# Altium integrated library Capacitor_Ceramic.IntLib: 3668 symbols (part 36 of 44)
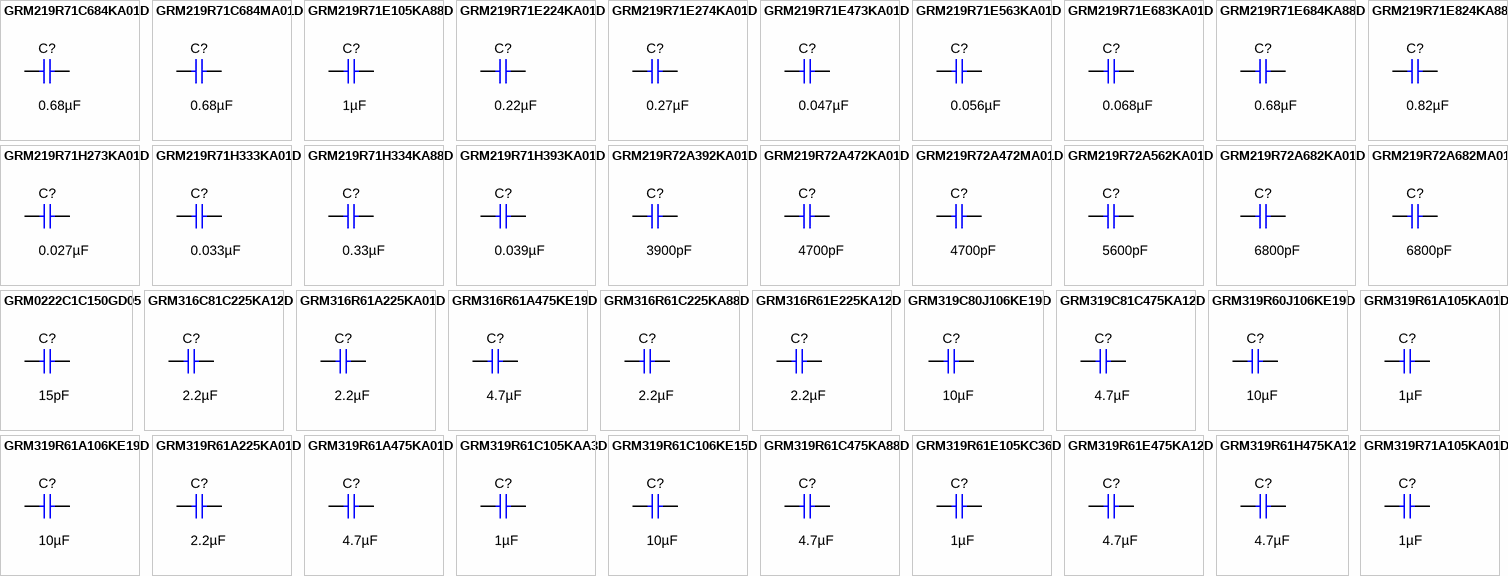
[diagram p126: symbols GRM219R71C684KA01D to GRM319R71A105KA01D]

## GRM219R71H334KA88D
designator C?  ValueDisplayed: 0.33µF  (hidden comment: GRM219R71H334KA88D)
CAP, CERM, 0.33 µF, 50 V,+/- 10%, X7R, 0805; Manufacturer: MuRata; Polarized: N; CompType: Capacitor; Value: 0.33uF; U/M: EA; Cap_F: 0.00000033; Tolerance_%: 10; VDC_V: 50; Value2: 50V; TaMin_C: -55; TaMax_C: 125; Cap_Case: 0805; SizeArea_mm2: 2.5; SizeAreaWB_mm2: 6.75; SizeX_mm: 2; SizeY_mm: 1.25; SizeZ_mm: 1.45; AEC Category: Q200; Green_Lifecycle: Active; Green_REACh: Passed
signal-integrity model Cap
simulation model Cap
footprint 0805_HV
footprint 0805_HV1
footprint 0805
footprint 0805M
footprint 0805L
pins: 1, 2

## GRM219R71H393KA01D
designator C?  ValueDisplayed: 0.039µF  (hidden comment: GRM219R71H393KA01D)
CAP, CERM, 0.039 µF, 50 V,+/- 10%, X7R, 0805; Manufacturer: MuRata; Polarized: N; CompType: Capacitor; Value: 0.039uF; U/M: EA; Cap_F: 0.000000039; Tolerance_%: 10; VDC_V: 50; Value2: 50V; TaMin_C: -55; TaMax_C: 125; Cap_Case: 0805; SizeArea_mm2: 2.5; SizeAreaWB_mm2: 6.75; SizeX_mm: 2; SizeY_mm: 1.25; SizeZ_mm: 1.45; AEC Category: Q200
signal-integrity model Cap
simulation model Cap
footprint 0805_HV
footprint 0805_HV1
footprint 0805
footprint 0805M
footprint 0805L
pins: 1, 2

## GRM219R72A392KA01D
designator C?  ValueDisplayed: 3900pF  (hidden comment: GRM219R72A392KA01D)
CAP, CERM, 3900 pF, 100 V,+/- 10%, X7R, 0805; Manufacturer: MuRata; Polarized: N; CompType: Capacitor; Value: 3900pF; U/M: EA; Cap_F: 0.0000000039; Tolerance_%: 10; VDC_V: 100; Value2: 100V; TaMin_C: -55; TaMax_C: 125; Cap_Case: 0805; SizeArea_mm2: 2.5; SizeAreaWB_mm2: 6.75; SizeX_mm: 2; SizeY_mm: 1.25; SizeZ_mm: 1.45; AEC Category: Q200
signal-integrity model Cap
simulation model Cap
footprint 0805_HV
footprint 0805_HV1
footprint 0805
footprint 0805M
footprint 0805L
pins: 1, 2

## GRM219R72A472KA01D
designator C?  ValueDisplayed: 4700pF  (hidden comment: GRM219R72A472KA01D)
CAP, CERM, 4700 pF, 100 V,+/- 10%, X7R, 0805; Manufacturer: MuRata; Polarized: N; CompType: Capacitor; Value: 4700pF; U/M: EA; Cap_F: 0.0000000047; Tolerance_%: 10; VDC_V: 100; Value2: 100V; TaMin_C: -55; TaMax_C: 125; Cap_Case: 0805; SizeArea_mm2: 2.5; SizeAreaWB_mm2: 6.75; SizeX_mm: 2; SizeY_mm: 1.25; SizeZ_mm: 1.45; AEC Category: Q200
signal-integrity model Cap
simulation model Cap
footprint 0805_HV
footprint 0805_HV1
footprint 0805
footprint 0805M
footprint 0805L
pins: 1, 2

## GRM219R72A472MA01D
designator C?  ValueDisplayed: 4700pF  (hidden comment: GRM219R72A472MA01D)
CAP, CERM, 4700 pF, 100 V,+/- 20%, X7R, 0805; Manufacturer: MuRata; Polarized: N; CompType: Capacitor; Value: 4700pF; U/M: EA; Cap_F: 0.0000000047; Tolerance_%: 20; VDC_V: 100; Value2: 100V; TaMin_C: -55; TaMax_C: 125; Cap_Case: 0805; SizeArea_mm2: 2.5; SizeAreaWB_mm2: 6.75; SizeX_mm: 2; SizeY_mm: 1.25; SizeZ_mm: 1.45; AEC Category: Q200
signal-integrity model Cap
simulation model Cap
footprint 0805_HV
footprint 0805_HV1
footprint 0805
footprint 0805M
footprint 0805L
pins: 1, 2

## GRM219R72A562KA01D
designator C?  ValueDisplayed: 5600pF  (hidden comment: GRM219R72A562KA01D)
CAP, CERM, 5600 pF, 100 V,+/- 10%, X7R, 0805; Manufacturer: MuRata; Polarized: N; CompType: Capacitor; Value: 5600pF; U/M: EA; Cap_F: 0.0000000056; Tolerance_%: 10; VDC_V: 100; Value2: 100V; TaMin_C: -55; TaMax_C: 125; Cap_Case: 0805; SizeArea_mm2: 2.5; SizeAreaWB_mm2: 6.75; SizeX_mm: 2; SizeY_mm: 1.25; SizeZ_mm: 1.45; AEC Category: Q200
signal-integrity model Cap
simulation model Cap
footprint 0805_HV
footprint 0805_HV1
footprint 0805
footprint 0805M
footprint 0805L
pins: 1, 2

## GRM219R72A682KA01D
designator C?  ValueDisplayed: 6800pF  (hidden comment: GRM219R72A682KA01D)
CAP, CERM, 6800 pF, 100 V,+/- 10%, X7R, 0805; Manufacturer: MuRata; Polarized: N; CompType: Capacitor; Value: 6800pF; U/M: EA; Cap_F: 0.0000000068; Tolerance_%: 10; VDC_V: 100; Value2: 100V; TaMin_C: -55; TaMax_C: 125; Cap_Case: 0805; SizeArea_mm2: 2.5; SizeAreaWB_mm2: 6.75; SizeX_mm: 2; SizeY_mm: 1.25; SizeZ_mm: 1.45; AEC Category: Q200
signal-integrity model Cap
simulation model Cap
footprint 0805_HV
footprint 0805_HV1
footprint 0805
footprint 0805M
footprint 0805L
pins: 1, 2

## GRM219R72A682MA01D
designator C?  ValueDisplayed: 6800pF  (hidden comment: GRM219R72A682MA01D)
CAP, CERM, 6800 pF, 100 V,+/- 20%, X7R, 0805; Manufacturer: MuRata; Polarized: N; CompType: Capacitor; Value: 6800pF; U/M: EA; Cap_F: 0.0000000068; Tolerance_%: 20; VDC_V: 100; Value2: 100V; TaMin_C: -55; TaMax_C: 125; Cap_Case: 0805; SizeArea_mm2: 2.5; SizeAreaWB_mm2: 6.75; SizeX_mm: 2; SizeY_mm: 1.25; SizeZ_mm: 1.45; AEC Category: Q200
signal-integrity model Cap
simulation model Cap
footprint 0805_HV
footprint 0805_HV1
footprint 0805
footprint 0805M
footprint 0805L
pins: 1, 2

## GRM0222C1C150GD05
designator C?  ValueDisplayed: 15pF  (hidden comment: GRM0222C1C150GD05)
CAP, CERM, 15 pF, 16 V,+/- 2%, C0G/NP0, 01005; Manufacturer: MuRata; Polarized: N; CompType: Capacitor; Value: 15pF; U/M: EA; Cap_F: 0.000000000015; Tolerance_%: 2; VDC_V: 16; Value2: 16V; TaMin_C: -55; TaMax_C: 125; Cap_Case: 01005; SizeArea_mm2: 0.08; SizeAreaWB_mm2: 1.68; SizeX_mm: 0.4; SizeY_mm: 0.2; AEC Category: Q200; Green_Lifecycle: Not Set; Green_REACh: Incomplete
signal-integrity model Cap
simulation model Cap
footprint 01005
pins: 1, 2

## GRM316C81C225KA12D
designator C?  ValueDisplayed: 2.2µF  (hidden comment: GRM316C81C225KA12D)
CAP, CERM, 2.2 µF, 16 V,+/- 10%, X6S, 1206; Manufacturer: MuRata; Polarized: N; CompType: Capacitor; Value: 2.2uF; U/M: EA; Cap_F: 0.0000022; Tolerance_%: 10; VDC_V: 16; Value2: 16V; TaMin_C: -55; TaMax_C: 105; Cap_Case: 1206; SizeArea_mm2: 5.12; SizeAreaWB_mm2: 10.92; SizeX_mm: 3.2; SizeY_mm: 1.6; SizeZ_mm: 1.35; AEC Category: Q200
signal-integrity model Cap
simulation model Cap
footprint 1206
footprint 1206M
footprint 1206L
pins: 1, 2

## GRM316R61A225KA01D
designator C?  ValueDisplayed: 2.2µF  (hidden comment: GRM316R61A225KA01D)
CAP, CERM, 2.2 µF, 10 V,+/- 10%, X5R, 1206; Manufacturer: MuRata; Polarized: N; CompType: Capacitor; Value: 2.2uF; U/M: EA; Cap_F: 0.0000022; Tolerance_%: 10; Value2: 10V; TaMin_C: -55; TaMax_C: 85; Cap_Case: 1206; SizeArea_mm2: 5.12; SizeAreaWB_mm2: 10.92; SizeX_mm: 3.2; SizeY_mm: 1.6; SizeZ_mm: 1.35; AEC Category: Q200
signal-integrity model Cap
simulation model Cap
footprint 1206
footprint 1206M
footprint 1206L
pins: 1, 2

## GRM316R61A475KE19D
designator C?  ValueDisplayed: 4.7µF  (hidden comment: GRM316R61A475KE19D)
CAP, CERM, 4.7 µF, 10 V,+/- 10%, X5R, 1206; Manufacturer: MuRata; Polarized: N; CompType: Capacitor; Value: 4.7uF; U/M: EA; Cap_F: 0.0000047; Tolerance_%: 10; ESR_ohm: 0.007; Value1: 0.007 ohm; Value2: 10V; TaMin_C: -55; TaMax_C: 85; Cap_Case: 1206; SizeArea_mm2: 5.12; SizeAreaWB_mm2: 10.92; SizeX_mm: 3.2; SizeY_mm: 1.6; SizeZ_mm: 1.35; AEC Category: Q200
signal-integrity model Cap
simulation model Cap
footprint 1206
footprint 1206M
footprint 1206L
pins: 1, 2

## GRM316R61C225KA88D
designator C?  ValueDisplayed: 2.2µF  (hidden comment: GRM316R61C225KA88D)
CAP, CERM, 2.2 µF, 16 V,+/- 10%, X5R, 1206; Manufacturer: MuRata; Polarized: N; CompType: Capacitor; Value: 2.2uF; U/M: EA; Cap_F: 0.0000022; Tolerance_%: 10; VDC_V: 16; Value2: 16V; TaMin_C: -55; TaMax_C: 85; Cap_Case: 1206; SizeArea_mm2: 5.12; SizeAreaWB_mm2: 10.92; SizeX_mm: 3.2; SizeY_mm: 1.6; SizeZ_mm: 1.35; AEC Category: Q200
signal-integrity model Cap
simulation model Cap
footprint 1206
footprint 1206M
footprint 1206L
pins: 1, 2

## GRM316R61E225KA12D
designator C?  ValueDisplayed: 2.2µF  (hidden comment: GRM316R61E225KA12D)
CAP, CERM, 2.2 µF, 25 V,+/- 10%, X5R, 1206; Manufacturer: MuRata; Polarized: N; CompType: Capacitor; Value: 2.2uF; U/M: EA; Cap_F: 0.0000022; Tolerance_%: 10; ESR_ohm: 0.006; Value1: 0.006 ohm; VDC_V: 25; Value2: 25V; TaMin_C: -55; TaMax_C: 85; Cap_Case: 1206; SizeArea_mm2: 5.12; SizeAreaWB_mm2: 10.92; SizeX_mm: 3.2; SizeY_mm: 1.6; SizeZ_mm: 1.35; AEC Category: Q200; Green_Lifecycle: Active; Green_REACh: Passed
signal-integrity model Cap
simulation model Cap
footprint 1206
footprint 1206M
footprint 1206L
pins: 1, 2

## GRM319C80J106KE19D
designator C?  ValueDisplayed: 10µF  (hidden comment: GRM319C80J106KE19D)
CAP, CERM, 10 µF, 6.3 V,+/- 10%, X6S, 1206; Manufacturer: MuRata; Polarized: N; CompType: Capacitor; Value: 10uF; U/M: EA; Cap_F: 0.00001; Tolerance_%: 10; VDC_V: 6.3; Value2: 6.3V; TaMin_C: -55; TaMax_C: 105; Cap_Case: 1206; SizeArea_mm2: 5.12; SizeAreaWB_mm2: 10.92; SizeX_mm: 3.2; SizeY_mm: 1.6; SizeZ_mm: 1.35; AEC Category: Q200
signal-integrity model Cap
simulation model Cap
footprint 1206
footprint 1206M
footprint 1206L
pins: 1, 2

## GRM319C81C475KA12D
designator C?  ValueDisplayed: 4.7µF  (hidden comment: GRM319C81C475KA12D)
CAP, CERM, 4.7 µF, 16 V,+/- 10%, X6S, 1206; Manufacturer: MuRata; Polarized: N; CompType: Capacitor; Value: 4.7uF; U/M: EA; Cap_F: 0.0000047; Tolerance_%: 10; VDC_V: 16; Value2: 16V; TaMin_C: -55; TaMax_C: 105; Cap_Case: 1206; SizeArea_mm2: 5.12; SizeAreaWB_mm2: 10.92; SizeX_mm: 3.2; SizeY_mm: 1.6; SizeZ_mm: 1.35; AEC Category: Q200
signal-integrity model Cap
simulation model Cap
footprint 1206
footprint 1206M
footprint 1206L
pins: 1, 2

## GRM319R60J106KE19D
designator C?  ValueDisplayed: 10µF  (hidden comment: GRM319R60J106KE19D)
CAP, CERM, 10 µF, 6.3 V,+/- 10%, X5R, 1206; Manufacturer: MuRata; Polarized: N; CompType: Capacitor; Value: 10uF; U/M: EA; Cap_F: 0.00001; Tolerance_%: 10; VDC_V: 6.3; Value2: 6.3V; TaMin_C: -55; TaMax_C: 85; Cap_Case: 1206; SizeArea_mm2: 5.12; SizeAreaWB_mm2: 10.92; SizeX_mm: 3.2; SizeY_mm: 1.6; SizeZ_mm: 1.35; AEC Category: Q200
signal-integrity model Cap
simulation model Cap
footprint 1206
footprint 1206M
footprint 1206L
pins: 1, 2

## GRM319R61A105KA01D
designator C?  ValueDisplayed: 1µF  (hidden comment: GRM319R61A105KA01D)
CAP, CERM, 1 µF, 10 V,+/- 10%, X5R, 1206; Manufacturer: MuRata; Polarized: N; CompType: Capacitor; Value: 1uF; U/M: EA; Cap_F: 0.000001; Tolerance_%: 10; Value2: 10V; TaMin_C: -55; TaMax_C: 85; Cap_Case: 1206; SizeArea_mm2: 5.12; SizeAreaWB_mm2: 10.92; SizeX_mm: 3.2; SizeY_mm: 1.6; SizeZ_mm: 1.35; AEC Category: Q200
signal-integrity model Cap
simulation model Cap
footprint 1206
footprint 1206M
footprint 1206L
pins: 1, 2

## GRM319R61A106KE19D
designator C?  ValueDisplayed: 10µF  (hidden comment: GRM319R61A106KE19D)
CAP, CERM, 10 µF, 10 V,+/- 10%, X5R, 1206; Manufacturer: MuRata; Polarized: N; CompType: Capacitor; Value: 10uF; U/M: EA; Cap_F: 0.00001; Tolerance_%: 10; ESR_ohm: 0.004; Value1: 0.004 ohm; Value2: 10V; TaMin_C: -55; TaMax_C: 85; Cap_Case: 1206; SizeArea_mm2: 5.12; SizeAreaWB_mm2: 10.92; SizeX_mm: 3.2; SizeY_mm: 1.6; SizeZ_mm: 1.35; AEC Category: Q200
signal-integrity model Cap
simulation model Cap
footprint 1206
footprint 1206M
footprint 1206L
pins: 1, 2

## GRM319R61A225KA01D
designator C?  ValueDisplayed: 2.2µF  (hidden comment: GRM319R61A225KA01D)
CAP, CERM, 2.2 µF, 10 V,+/- 10%, X5R, 1206; Manufacturer: MuRata; Polarized: N; CompType: Capacitor; Value: 2.2uF; U/M: EA; Cap_F: 0.0000022; Tolerance_%: 10; ESR_ohm: 0.009; Value1: 0.009 ohm; Value2: 10V; TaMin_C: -55; TaMax_C: 85; Cap_Case: 1206; SizeArea_mm2: 5.12; SizeAreaWB_mm2: 10.92; SizeX_mm: 3.2; SizeY_mm: 1.6; SizeZ_mm: 1.35; AEC Category: Q200
signal-integrity model Cap
simulation model Cap
footprint 1206
footprint 1206M
footprint 1206L
pins: 1, 2

## GRM319R61A475KA01D
designator C?  ValueDisplayed: 4.7µF  (hidden comment: GRM319R61A475KA01D)
CAP, CERM, 4.7 µF, 10 V,+/- 10%, X5R, 1206; Manufacturer: MuRata; Polarized: N; CompType: Capacitor; Value: 4.7uF; U/M: EA; Cap_F: 0.0000047; Tolerance_%: 10; Value2: 10V; TaMin_C: -55; TaMax_C: 85; Cap_Case: 1206; SizeArea_mm2: 5.12; SizeAreaWB_mm2: 10.92; SizeX_mm: 3.2; SizeY_mm: 1.6; SizeZ_mm: 1.35; AEC Category: Q200
signal-integrity model Cap
simulation model Cap
footprint 1206
footprint 1206M
footprint 1206L
pins: 1, 2

## GRM319R61C105KAA3D
designator C?  ValueDisplayed: 1µF  (hidden comment: GRM319R61C105KAA3D)
CAP, CERM, 1 µF, 16 V,+/- 10%, X5R, 1206; Manufacturer: MuRata; Polarized: N; CompType: Capacitor; Value: 1uF; U/M: EA; Cap_F: 0.000001; Tolerance_%: 10; VDC_V: 16; Value2: 16V; TaMin_C: -55; TaMax_C: 85; Cap_Case: 1206; SizeArea_mm2: 5.12; SizeAreaWB_mm2: 10.92; SizeX_mm: 3.2; SizeY_mm: 1.6; SizeZ_mm: 1.35; AEC Category: Q200
signal-integrity model Cap
simulation model Cap
footprint 1206
footprint 1206M
footprint 1206L
pins: 1, 2

## GRM319R61C106KE15D
designator C?  ValueDisplayed: 10µF  (hidden comment: GRM319R61C106KE15D)
CAP, CERM, 10 µF, 16 V,+/- 10%, X5R, 1206; Manufacturer: MuRata; Polarized: N; CompType: Capacitor; Value: 10uF; U/M: EA; Cap_F: 0.00001; Tolerance_%: 10; VDC_V: 16; Value2: 16V; TaMin_C: -55; TaMax_C: 85; Cap_Case: 1206; SizeArea_mm2: 5.12; SizeAreaWB_mm2: 10.92; SizeX_mm: 3.2; SizeY_mm: 1.6; SizeZ_mm: 1.35; AEC Category: Q200
signal-integrity model Cap
simulation model Cap
footprint 1206
footprint 1206M
footprint 1206L
pins: 1, 2

## GRM319R61C475KA88D
designator C?  ValueDisplayed: 4.7µF  (hidden comment: GRM319R61C475KA88D)
CAP, CERM, 4.7 µF, 16 V,+/- 10%, X5R, 1206; Manufacturer: MuRata; Polarized: N; CompType: Capacitor; Value: 4.7uF; U/M: EA; Cap_F: 0.0000047; Tolerance_%: 10; VDC_V: 16; Value2: 16V; TaMin_C: -55; TaMax_C: 85; Cap_Case: 1206; SizeArea_mm2: 5.12; SizeAreaWB_mm2: 10.92; SizeX_mm: 3.2; SizeY_mm: 1.6; SizeZ_mm: 1.35; AEC Category: Q200
signal-integrity model Cap
simulation model Cap
footprint 1206
footprint 1206M
footprint 1206L
pins: 1, 2

## GRM319R61E105KC36D
designator C?  ValueDisplayed: 1µF  (hidden comment: GRM319R61E105KC36D)
CAP, CERM, 1 µF, 25 V,+/- 10%, X5R, 1206; Manufacturer: MuRata; Polarized: N; CompType: Capacitor; Value: 1uF; U/M: EA; Cap_F: 0.000001; Tolerance_%: 10; ESR_ohm: 0.01; Value1: 0.01 ohm; VDC_V: 25; Value2: 25V; TaMin_C: -55; TaMax_C: 85; Cap_Case: 1206; SizeArea_mm2: 5.12; SizeAreaWB_mm2: 10.92; SizeX_mm: 3.2; SizeY_mm: 1.6; SizeZ_mm: 1.35; AEC Category: Q200
signal-integrity model Cap
simulation model Cap
footprint 1206
footprint 1206M
footprint 1206L
pins: 1, 2

## GRM319R61E475KA12D
designator C?  ValueDisplayed: 4.7µF  (hidden comment: GRM319R61E475KA12D)
CAP, CERM, 4.7 µF, 25 V,+/- 10%, X5R, 1206; Manufacturer: MuRata; Polarized: N; CompType: Capacitor; Value: 4.7uF; U/M: EA; Cap_F: 0.0000047; Tolerance_%: 10; ESR_ohm: 0.006; Value1: 0.006 ohm; VDC_V: 25; Value2: 25V; TaMin_C: -55; TaMax_C: 85; Cap_Case: 1206; SizeArea_mm2: 5.12; SizeAreaWB_mm2: 10.92; SizeX_mm: 3.2; SizeY_mm: 1.6; SizeZ_mm: 1.35; AEC Category: Q200
signal-integrity model Cap
simulation model Cap
footprint 1206
footprint 1206M
footprint 1206L
pins: 1, 2

## GRM319R61H475KA12
designator C?  ValueDisplayed: 4.7µF  (hidden comment: GRM319R61H475KA12)
CAP, CERM, 4.7 µF, 50 V,+/- 10%, X5R, 1206; Manufacturer: MuRata; Polarized: N; CompType: Capacitor; Value: 4.7uF; U/M: EA; Cap_F: 0.0000047; Tolerance_%: 10; VDC_V: 50; Value2: 50V; TaMin_C: -55; TaMax_C: 85; Cap_Case: 1206; SizeArea_mm2: 5.12; SizeAreaWB_mm2: 10.92; SizeX_mm: 3.2; SizeY_mm: 1.6; SizeZ_mm: 1.35; AEC Category: Q200; Green_Lifecycle: Active; Green_REACh: Passed
signal-integrity model Cap
simulation model Cap
footprint 1206
footprint 1206M
footprint 1206L
pins: 1, 2

## GRM319R71A105KA01D
designator C?  ValueDisplayed: 1µF  (hidden comment: GRM319R71A105KA01D)
CAP, CERM, 1 µF, 10 V,+/- 10%, X7R, 1206; Manufacturer: MuRata; Polarized: N; CompType: Capacitor; Value: 1uF; U/M: EA; Cap_F: 0.000001; Tolerance_%: 10; Value2: 10V; TaMin_C: -55; TaMax_C: 125; Cap_Case: 1206; SizeArea_mm2: 5.12; SizeAreaWB_mm2: 10.92; SizeX_mm: 3.2; SizeY_mm: 1.6; SizeZ_mm: 1.35; AEC Category: Q200
signal-integrity model Cap
simulation model Cap
footprint 1206
footprint 1206M
footprint 1206L
pins: 1, 2

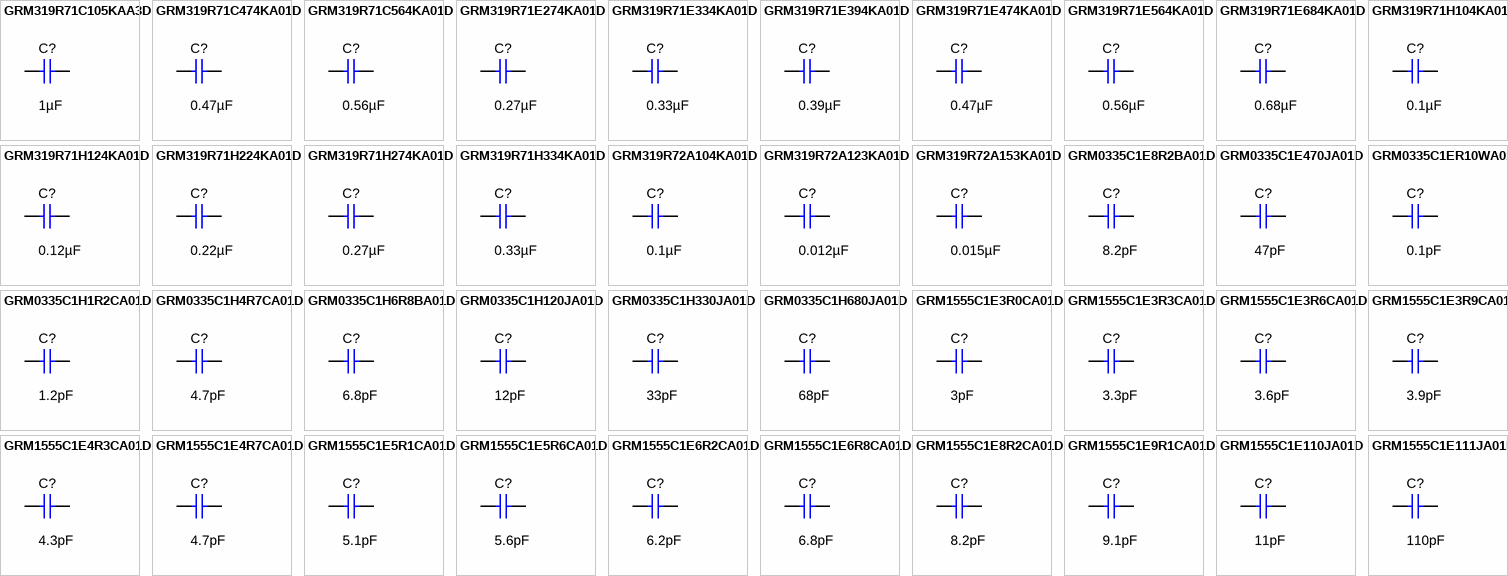
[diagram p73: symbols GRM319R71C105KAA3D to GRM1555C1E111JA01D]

## GRM319R71C105KAA3D
designator C?  ValueDisplayed: 1µF  (hidden comment: GRM319R71C105KAA3D)
CAP, CERM, 1 µF, 16 V,+/- 10%, X7R, 1206; Manufacturer: MuRata; Polarized: N; CompType: Capacitor; Value: 1uF; U/M: EA; Cap_F: 0.000001; Tolerance_%: 10; VDC_V: 16; Value2: 16V; TaMin_C: -55; TaMax_C: 125; Cap_Case: 1206; SizeArea_mm2: 5.12; SizeAreaWB_mm2: 10.92; SizeX_mm: 3.2; SizeY_mm: 1.6; SizeZ_mm: 1.35; AEC Category: Q200
signal-integrity model Cap
simulation model Cap
footprint 1206
footprint 1206M
footprint 1206L
pins: 1, 2

## GRM319R71C474KA01D
designator C?  ValueDisplayed: 0.47µF  (hidden comment: GRM319R71C474KA01D)
CAP, CERM, 0.47 µF, 16 V,+/- 10%, X7R, 1206; Manufacturer: MuRata; Polarized: N; CompType: Capacitor; Value: 0.47uF; U/M: EA; Cap_F: 0.00000047; Tolerance_%: 10; VDC_V: 16; Value2: 16V; TaMin_C: -55; TaMax_C: 125; Cap_Case: 1206; SizeArea_mm2: 5.12; SizeAreaWB_mm2: 10.92; SizeX_mm: 3.2; SizeY_mm: 1.6; SizeZ_mm: 1.35; AEC Category: Q200
signal-integrity model Cap
simulation model Cap
footprint 1206
footprint 1206M
footprint 1206L
pins: 1, 2

## GRM319R71C564KA01D
designator C?  ValueDisplayed: 0.56µF  (hidden comment: GRM319R71C564KA01D)
CAP, CERM, 0.56 µF, 16 V,+/- 10%, X7R, 1206; Manufacturer: MuRata; Polarized: N; CompType: Capacitor; Value: 0.56uF; U/M: EA; Cap_F: 0.00000056; Tolerance_%: 10; VDC_V: 16; Value2: 16V; TaMin_C: -55; TaMax_C: 125; Cap_Case: 1206; SizeArea_mm2: 5.12; SizeAreaWB_mm2: 10.92; SizeX_mm: 3.2; SizeY_mm: 1.6; SizeZ_mm: 1.35; AEC Category: Q200
signal-integrity model Cap
simulation model Cap
footprint 1206
footprint 1206M
footprint 1206L
pins: 1, 2

## GRM319R71E274KA01D
designator C?  ValueDisplayed: 0.27µF  (hidden comment: GRM319R71E274KA01D)
CAP, CERM, 0.27 µF, 25 V,+/- 10%, X7R, 1206; Manufacturer: MuRata; Polarized: N; CompType: Capacitor; Value: 0.27uF; U/M: EA; Cap_F: 0.00000027; Tolerance_%: 10; VDC_V: 25; Value2: 25V; TaMin_C: -55; TaMax_C: 125; Cap_Case: 1206; SizeArea_mm2: 5.12; SizeAreaWB_mm2: 10.92; SizeX_mm: 3.2; SizeY_mm: 1.6; SizeZ_mm: 1.35; AEC Category: Q200
signal-integrity model Cap
simulation model Cap
footprint 1206
footprint 1206M
footprint 1206L
pins: 1, 2

## GRM319R71E334KA01D
designator C?  ValueDisplayed: 0.33µF  (hidden comment: GRM319R71E334KA01D)
CAP, CERM, 0.33 µF, 25 V,+/- 10%, X7R, 1206; Manufacturer: MuRata; Polarized: N; CompType: Capacitor; Value: 0.33uF; U/M: EA; Cap_F: 0.00000033; Tolerance_%: 10; VDC_V: 25; Value2: 25V; TaMin_C: -55; TaMax_C: 125; Cap_Case: 1206; SizeArea_mm2: 5.12; SizeAreaWB_mm2: 10.92; SizeX_mm: 3.2; SizeY_mm: 1.6; SizeZ_mm: 1.35; AEC Category: Q200
signal-integrity model Cap
simulation model Cap
footprint 1206
footprint 1206M
footprint 1206L
pins: 1, 2

## GRM319R71E394KA01D
designator C?  ValueDisplayed: 0.39µF  (hidden comment: GRM319R71E394KA01D)
CAP, CERM, 0.39 µF, 25 V,+/- 10%, X7R, 1206; Manufacturer: MuRata; Polarized: N; CompType: Capacitor; Value: 0.39uF; U/M: EA; Cap_F: 0.00000039; Tolerance_%: 10; VDC_V: 25; Value2: 25V; TaMin_C: -55; TaMax_C: 125; Cap_Case: 1206; SizeArea_mm2: 5.12; SizeAreaWB_mm2: 10.92; SizeX_mm: 3.2; SizeY_mm: 1.6; SizeZ_mm: 1.35; AEC Category: Q200
signal-integrity model Cap
simulation model Cap
footprint 1206
footprint 1206M
footprint 1206L
pins: 1, 2

## GRM319R71E474KA01D
designator C?  ValueDisplayed: 0.47µF  (hidden comment: GRM319R71E474KA01D)
CAP, CERM, 0.47 µF, 25 V,+/- 10%, X7R, 1206; Manufacturer: MuRata; Polarized: N; CompType: Capacitor; Value: 0.47uF; U/M: EA; Cap_F: 0.00000047; Tolerance_%: 10; VDC_V: 25; Value2: 25V; TaMin_C: -55; TaMax_C: 125; Cap_Case: 1206; SizeArea_mm2: 5.12; SizeAreaWB_mm2: 10.92; SizeX_mm: 3.2; SizeY_mm: 1.6; SizeZ_mm: 1.35; AEC Category: Q200
signal-integrity model Cap
simulation model Cap
footprint 1206
footprint 1206M
footprint 1206L
pins: 1, 2

## GRM319R71E564KA01D
designator C?  ValueDisplayed: 0.56µF  (hidden comment: GRM319R71E564KA01D)
CAP, CERM, 0.56 µF, 25 V,+/- 10%, X7R, 1206; Manufacturer: MuRata; Polarized: N; CompType: Capacitor; Value: 0.56uF; U/M: EA; Cap_F: 0.00000056; Tolerance_%: 10; VDC_V: 25; Value2: 25V; TaMin_C: -55; TaMax_C: 125; Cap_Case: 1206; SizeArea_mm2: 5.12; SizeAreaWB_mm2: 10.92; SizeX_mm: 3.2; SizeY_mm: 1.6; SizeZ_mm: 1.35; AEC Category: Q200
signal-integrity model Cap
simulation model Cap
footprint 1206
footprint 1206M
footprint 1206L
pins: 1, 2

## GRM319R71E684KA01D
designator C?  ValueDisplayed: 0.68µF  (hidden comment: GRM319R71E684KA01D)
CAP, CERM, 0.68 µF, 25 V,+/- 10%, X7R, 1206; Manufacturer: MuRata; Polarized: N; CompType: Capacitor; Value: 0.68uF; U/M: EA; Cap_F: 0.00000068; Tolerance_%: 10; VDC_V: 25; Value2: 25V; TaMin_C: -55; TaMax_C: 125; Cap_Case: 1206; SizeArea_mm2: 5.12; SizeAreaWB_mm2: 10.92; SizeX_mm: 3.2; SizeY_mm: 1.6; SizeZ_mm: 1.35; AEC Category: Q200
signal-integrity model Cap
simulation model Cap
footprint 1206
footprint 1206M
footprint 1206L
pins: 1, 2

## GRM319R71H104KA01D
designator C?  ValueDisplayed: 0.1µF  (hidden comment: GRM319R71H104KA01D)
CAP, CERM, 0.1 µF, 50 V,+/- 10%, X7R, 1206; Manufacturer: MuRata; Polarized: N; CompType: Capacitor; Value: 0.1uF; U/M: EA; Cap_F: 0.0000001; Tolerance_%: 10; ESR_ohm: 0.01; Value1: 0.01 ohm; VDC_V: 50; Value2: 50V; IRMS_A: 0.9; TaMin_C: -55; TaMax_C: 125; Cap_Case: 1206; SizeArea_mm2: 5.12; SizeAreaWB_mm2: 10.92; SizeX_mm: 3.2; SizeY_mm: 1.6; SizeZ_mm: 1.35; AEC Category: Q200; Green_Lifecycle: Active; Green_REACh: Passed
signal-integrity model Cap
simulation model Cap
footprint 1206
footprint 1206M
footprint 1206L
pins: 1, 2

## GRM319R71H124KA01D
designator C?  ValueDisplayed: 0.12µF  (hidden comment: GRM319R71H124KA01D)
CAP, CERM, 0.12 µF, 50 V,+/- 10%, X7R, 1206; Manufacturer: MuRata; Polarized: N; CompType: Capacitor; Value: 0.12uF; U/M: EA; Cap_F: 0.00000012; Tolerance_%: 10; VDC_V: 50; Value2: 50V; TaMin_C: -55; TaMax_C: 125; Cap_Case: 1206; SizeArea_mm2: 5.12; SizeAreaWB_mm2: 10.92; SizeX_mm: 3.2; SizeY_mm: 1.6; SizeZ_mm: 1.35; AEC Category: Q200
signal-integrity model Cap
simulation model Cap
footprint 1206
footprint 1206M
footprint 1206L
pins: 1, 2

## GRM319R71H224KA01D
designator C?  ValueDisplayed: 0.22µF  (hidden comment: GRM319R71H224KA01D)
CAP, CERM, 0.22 µF, 50 V,+/- 10%, X7R, 1206; Manufacturer: MuRata; Polarized: N; CompType: Capacitor; Value: 0.22uF; U/M: EA; Cap_F: 0.00000022; Tolerance_%: 10; ESR_ohm: 0.01; Value1: 0.01 ohm; VDC_V: 50; Value2: 50V; IRMS_A: 0.9; TaMin_C: -55; TaMax_C: 125; Cap_Case: 1206; SizeArea_mm2: 5.12; SizeAreaWB_mm2: 10.92; SizeX_mm: 3.2; SizeY_mm: 1.6; SizeZ_mm: 1.35; AEC Category: Q200
signal-integrity model Cap
simulation model Cap
footprint 1206
footprint 1206M
footprint 1206L
pins: 1, 2

## GRM319R71H274KA01D
designator C?  ValueDisplayed: 0.27µF  (hidden comment: GRM319R71H274KA01D)
CAP, CERM, 0.27 µF, 50 V,+/- 10%, X7R, 1206; Manufacturer: MuRata; Polarized: N; CompType: Capacitor; Value: 0.27uF; U/M: EA; Cap_F: 0.00000027; Tolerance_%: 10; VDC_V: 50; Value2: 50V; TaMin_C: -55; TaMax_C: 125; Cap_Case: 1206; SizeArea_mm2: 5.12; SizeAreaWB_mm2: 10.92; SizeX_mm: 3.2; SizeY_mm: 1.6; SizeZ_mm: 1.35; AEC Category: Q200
signal-integrity model Cap
simulation model Cap
footprint 1206
footprint 1206M
footprint 1206L
pins: 1, 2

## GRM319R71H334KA01D
designator C?  ValueDisplayed: 0.33µF  (hidden comment: GRM319R71H334KA01D)
CAP, CERM, 0.33 µF, 50 V,+/- 10%, X7R, 1206; Manufacturer: MuRata; Polarized: N; CompType: Capacitor; Value: 0.33uF; U/M: EA; Cap_F: 0.00000033; Tolerance_%: 10; VDC_V: 50; Value2: 50V; TaMin_C: -55; TaMax_C: 125; Cap_Case: 1206; SizeArea_mm2: 5.12; SizeAreaWB_mm2: 10.92; SizeX_mm: 3.2; SizeY_mm: 1.6; SizeZ_mm: 1.35; AEC Category: Q200; Green_Lifecycle: Active; Green_REACh: Passed
signal-integrity model Cap
simulation model Cap
footprint 1206
footprint 1206M
footprint 1206L
pins: 1, 2

## GRM319R72A104KA01D
designator C?  ValueDisplayed: 0.1µF  (hidden comment: GRM319R72A104KA01D)
CAP, CERM, 0.1 µF, 100 V,+/- 10%, X7R, 1206; Manufacturer: MuRata; Polarized: N; CompType: Capacitor; Value: 0.1uF; U/M: EA; Cap_F: 0.0000001; Tolerance_%: 10; VDC_V: 100; Value2: 100V; TaMin_C: -55; TaMax_C: 125; Cap_Case: 1206; SizeArea_mm2: 5.12; SizeAreaWB_mm2: 10.92; SizeX_mm: 3.2; SizeY_mm: 1.6; SizeZ_mm: 1.35; AEC Category: Q200
signal-integrity model Cap
simulation model Cap
footprint 1206
footprint 1206M
footprint 1206L
pins: 1, 2

## GRM319R72A123KA01D
designator C?  ValueDisplayed: 0.012µF  (hidden comment: GRM319R72A123KA01D)
CAP, CERM, 0.012 µF, 100 V,+/- 10%, X7R, 1206; Manufacturer: MuRata; Polarized: N; CompType: Capacitor; Value: 0.012uF; U/M: EA; Cap_F: 0.000000012; Tolerance_%: 10; VDC_V: 100; Value2: 100V; TaMin_C: -55; TaMax_C: 125; Cap_Case: 1206; SizeArea_mm2: 5.12; SizeAreaWB_mm2: 10.92; SizeX_mm: 3.2; SizeY_mm: 1.6; SizeZ_mm: 1.35; AEC Category: Q200
signal-integrity model Cap
simulation model Cap
footprint 1206
footprint 1206M
footprint 1206L
pins: 1, 2

## GRM319R72A153KA01D
designator C?  ValueDisplayed: 0.015µF  (hidden comment: GRM319R72A153KA01D)
CAP, CERM, 0.015 µF, 100 V,+/- 10%, X7R, 1206; Manufacturer: MuRata; Polarized: N; CompType: Capacitor; Value: 0.015uF; U/M: EA; Cap_F: 0.000000015; Tolerance_%: 10; VDC_V: 100; Value2: 100V; TaMin_C: -55; TaMax_C: 125; Cap_Case: 1206; SizeArea_mm2: 5.12; SizeAreaWB_mm2: 10.92; SizeX_mm: 3.2; SizeY_mm: 1.6; SizeZ_mm: 1.35; AEC Category: Q200
signal-integrity model Cap
simulation model Cap
footprint 1206
footprint 1206M
footprint 1206L
pins: 1, 2

## GRM0335C1E8R2BA01D
designator C?  ValueDisplayed: 8.2pF  (hidden comment: GRM0335C1E8R2BA01D)
CAP, CERM, 8.2 pF, 25 V,+/- 1.2%, C0G/NP0, 0201; Manufacturer: MuRata; Polarized: N; CompType: Capacitor; Value: 8.2pF; U/M: EA; Cap_F: 0.0000000000082; Tolerance_%: 1.2; VDC_V: 25; Value2: 25V; TaMin_C: -55; TaMax_C: 125; Cap_Case: 0201; SizeArea_mm2: 0.18; SizeAreaWB_mm2: 2.08; SizeX_mm: 0.6; SizeY_mm: 0.3; SizeZ_mm: 0.26; AEC Category: Q200
signal-integrity model Cap
simulation model Cap
footprint 0201
footprint 0201M
footprint 0201L
footprint 0201_Silk
pins: 1, 2

## GRM0335C1E470JA01D
designator C?  ValueDisplayed: 47pF  (hidden comment: GRM0335C1E470JA01D)
CAP, CERM, 47 pF, 25 V,+/- 5%, C0G/NP0, 0201; Manufacturer: MuRata; Polarized: N; CompType: Capacitor; Value: 47pF; U/M: EA; Cap_F: 0.000000000047; Tolerance_%: 5; VDC_V: 25; Value2: 25V; TaMin_C: -55; TaMax_C: 125; Cap_Case: 0201; SizeArea_mm2: 0.18; SizeAreaWB_mm2: 2.08; SizeX_mm: 0.6; SizeY_mm: 0.3; SizeZ_mm: 0.33; AEC Category: Q200; Green_Lifecycle: Active; Green_REACh: Passed
signal-integrity model Cap
simulation model Cap
footprint 0201_033
footprint 0201_033M
footprint 0201_033L
pins: 1, 2

## GRM0335C1ER10WA01D
designator C?  ValueDisplayed: 0.1pF  (hidden comment: GRM0335C1ER10WA01D)
CAP, CERM, 0.1pF, 25 V,+/- 50%, C0G/NP0, 0201; Manufacturer: MuRata; Polarized: N; CompType: Capacitor; U/M: EA; Cap_F: 0.0000000000001; Tolerance_%: 50; VDC_V: 25; Value2: 25V; TaMin_C: -55; TaMax_C: 125; Cap_Case: 0201; SizeArea_mm2: 0.18; SizeAreaWB_mm2: 2.08; SizeX_mm: 0.6; SizeY_mm: 0.3; SizeZ_mm: 0.33; AEC Category: Q200; Green_Lifecycle: Active; Green_REACh: Passed
signal-integrity model Cap
simulation model Cap
footprint 0201_033
footprint 0201_033M
footprint 0201_033L
pins: 1, 2

## GRM0335C1H1R2CA01D
designator C?  ValueDisplayed: 1.2pF  (hidden comment: GRM0335C1H1R2CA01D)
CAP, CERM, 1.2 pF, 50 V,+/- 20%, C0G/NP0, 0201; Manufacturer: MuRata; Polarized: N; CompType: Capacitor; Value: 1.2pF; U/M: EA; Cap_F: 0.0000000000012; Tolerance_%: 20; VDC_V: 50; Value2: 50V; TaMin_C: -55; TaMax_C: 125; Cap_Case: 0201; SizeArea_mm2: 0.18; SizeAreaWB_mm2: 2.08; SizeX_mm: 0.6; SizeY_mm: 0.3; SizeZ_mm: 0.26; AEC Category: Q200
signal-integrity model Cap
simulation model Cap
footprint 0201
footprint 0201M
footprint 0201L
footprint 0201_Silk
pins: 1, 2

## GRM0335C1H4R7CA01D
designator C?  ValueDisplayed: 4.7pF  (hidden comment: GRM0335C1H4R7CA01D)
CAP, CERM, 4.7 pF, 50 V,+/- 5%, C0G/NP0, 0201; Manufacturer: MuRata; Polarized: N; CompType: Capacitor; Value: 4.7pF; U/M: EA; Cap_F: 0.0000000000047; Tolerance_%: 5; VDC_V: 50; Value2: 50V; TaMin_C: -55; TaMax_C: 125; Cap_Case: 0201; SizeArea_mm2: 0.18; SizeAreaWB_mm2: 2.08; SizeX_mm: 0.6; SizeY_mm: 0.3; SizeZ_mm: 0.26; AEC Category: Q200
signal-integrity model Cap
simulation model Cap
footprint 0201
footprint 0201M
footprint 0201L
footprint 0201_Silk
pins: 1, 2

## GRM0335C1H6R8BA01D
designator C?  ValueDisplayed: 6.8pF  (hidden comment: GRM0335C1H6R8BA01D)
CAP, CERM, 6.8 pF, 50 V,+/- 2%, C0G/NP0, 0201; Manufacturer: MuRata; Polarized: N; CompType: Capacitor; Value: 6.8pF; U/M: EA; Cap_F: 0.0000000000068; Tolerance_%: 2; VDC_V: 50; Value2: 50V; TaMin_C: -55; TaMax_C: 125; Cap_Case: 0201; SizeArea_mm2: 0.18; SizeAreaWB_mm2: 2.08; SizeX_mm: 0.6; SizeY_mm: 0.3; SizeZ_mm: 0.26; AEC Category: Q200
signal-integrity model Cap
simulation model Cap
footprint 0201
footprint 0201M
footprint 0201L
footprint 0201_Silk
pins: 1, 2

## GRM0335C1H120JA01D
designator C?  ValueDisplayed: 12pF  (hidden comment: GRM0335C1H120JA01D)
CAP, CERM, 12 pF, 50 V,+/- 5%, C0G/NP0, 0201; Manufacturer: MuRata; Polarized: N; CompType: Capacitor; Value: 12pF; U/M: EA; Cap_F: 0.000000000012; Tolerance_%: 5; VDC_V: 50; Value2: 50V; TaMin_C: -55; TaMax_C: 125; Cap_Case: 0201; SizeArea_mm2: 0.18; SizeAreaWB_mm2: 2.08; SizeX_mm: 0.6; SizeY_mm: 0.3; SizeZ_mm: 0.26; AEC Category: Q200
signal-integrity model Cap
simulation model Cap
footprint 0201
footprint 0201M
footprint 0201L
footprint 0201_Silk
pins: 1, 2

## GRM0335C1H330JA01D
designator C?  ValueDisplayed: 33pF  (hidden comment: GRM0335C1H330JA01D)
CAP, CERM, 33 pF, 50 V,+/- 5%, C0G/NP0, 0201; Manufacturer: MuRata; Polarized: N; CompType: Capacitor; Value: 33pF; U/M: EA; Cap_F: 0.000000000033; Tolerance_%: 5; VDC_V: 50; Value2: 50V; TaMin_C: -55; TaMax_C: 125; Cap_Case: 0201; SizeArea_mm2: 0.18; SizeAreaWB_mm2: 2.08; SizeX_mm: 0.6; SizeY_mm: 0.3; SizeZ_mm: 0.26; AEC Category: Q200
signal-integrity model Cap
simulation model Cap
footprint 0201
footprint 0201M
footprint 0201L
footprint 0201_Silk
pins: 1, 2

## GRM0335C1H680JA01D
designator C?  ValueDisplayed: 68pF  (hidden comment: GRM0335C1H680JA01D)
CAP, CERM, 68 pF, 50 V,+/- 5%, C0G/NP0, 0201; Manufacturer: MuRata; Polarized: N; CompType: Capacitor; Value: 68pF; U/M: EA; Cap_F: 0.000000000068; Tolerance_%: 5; VDC_V: 50; Value2: 50V; TaMin_C: -55; TaMax_C: 125; Cap_Case: 0201; SizeArea_mm2: 0.18; SizeAreaWB_mm2: 2.08; SizeX_mm: 0.6; SizeY_mm: 0.3; SizeZ_mm: 0.33; AEC Category: Q200
signal-integrity model Cap
simulation model Cap
footprint 0201_033
footprint 0201_033M
footprint 0201_033L
pins: 1, 2

## GRM1555C1E3R0CA01D
designator C?  ValueDisplayed: 3pF  (hidden comment: GRM1555C1E3R0CA01D)
CAP, CERM, 3 pF, 25 V,+/- 5%, C0G/NP0, 0402; Manufacturer: MuRata; Polarized: N; CompType: Capacitor; Value: 3pF; U/M: EA; Cap_F: 0.000000000003; Tolerance_%: 5; VDC_V: 25; Value2: 25V; TaMin_C: -55; TaMax_C: 125; Cap_Case: 0402; SizeArea_mm2: 0.5; SizeAreaWB_mm2: 3; SizeX_mm: 1; SizeZ_mm: 0.6; AEC Category: Q200
signal-integrity model Cap
simulation model Cap
footprint 0402
footprint 0402M
footprint 0402L
footprint 0402S
pins: 1, 2

## GRM1555C1E3R3CA01D
designator C?  ValueDisplayed: 3.3pF  (hidden comment: GRM1555C1E3R3CA01D)
CAP, CERM, 3.3 pF, 25 V,+/- 5%, C0G/NP0, 0402; Manufacturer: MuRata; Polarized: N; CompType: Capacitor; Value: 3.3pF; U/M: EA; Cap_F: 0.0000000000033; Tolerance_%: 5; VDC_V: 25; Value2: 25V; TaMin_C: -55; TaMax_C: 125; Cap_Case: 0402; SizeArea_mm2: 0.5; SizeAreaWB_mm2: 3; SizeX_mm: 1; SizeZ_mm: 0.6; AEC Category: Q200
signal-integrity model Cap
simulation model Cap
footprint 0402
footprint 0402M
footprint 0402L
footprint 0402S
pins: 1, 2

## GRM1555C1E3R6CA01D
designator C?  ValueDisplayed: 3.6pF  (hidden comment: GRM1555C1E3R6CA01D)
CAP, CERM, 3.6 pF, 25 V,+/- 5%, C0G/NP0, 0402; Manufacturer: MuRata; Polarized: N; CompType: Capacitor; Value: 3.6pF; U/M: EA; Cap_F: 0.0000000000036; Tolerance_%: 5; VDC_V: 25; Value2: 25V; TaMin_C: -55; TaMax_C: 125; Cap_Case: 0402; SizeArea_mm2: 0.5; SizeAreaWB_mm2: 3; SizeX_mm: 1; SizeZ_mm: 0.6; AEC Category: Q200
signal-integrity model Cap
simulation model Cap
footprint 0402
footprint 0402M
footprint 0402L
footprint 0402S
pins: 1, 2

## GRM1555C1E3R9CA01D
designator C?  ValueDisplayed: 3.9pF  (hidden comment: GRM1555C1E3R9CA01D)
CAP, CERM, 3.9 pF, 25 V,+/- 5%, C0G/NP0, 0402; Manufacturer: MuRata; Polarized: N; CompType: Capacitor; Value: 3.9pF; U/M: EA; Cap_F: 0.0000000000039; Tolerance_%: 5; VDC_V: 25; Value2: 25V; TaMin_C: -55; TaMax_C: 125; Cap_Case: 0402; SizeArea_mm2: 0.5; SizeAreaWB_mm2: 3; SizeX_mm: 1; SizeZ_mm: 0.6; AEC Category: Q200; Green_Lifecycle: Active; Green_REACh: Passed
signal-integrity model Cap
simulation model Cap
footprint 0402
footprint 0402M
footprint 0402L
footprint 0402S
pins: 1, 2

## GRM1555C1E4R3CA01D
designator C?  ValueDisplayed: 4.3pF  (hidden comment: GRM1555C1E4R3CA01D)
CAP, CERM, 4.3 pF, 25 V,+/- 5%, C0G/NP0, 0402; Manufacturer: MuRata; Polarized: N; CompType: Capacitor; Value: 4.3pF; U/M: EA; Cap_F: 0.0000000000043; Tolerance_%: 5; VDC_V: 25; Value2: 25V; TaMin_C: -55; TaMax_C: 125; Cap_Case: 0402; SizeArea_mm2: 0.5; SizeAreaWB_mm2: 3; SizeX_mm: 1; SizeZ_mm: 0.6; AEC Category: Q200
signal-integrity model Cap
simulation model Cap
footprint 0402
footprint 0402M
footprint 0402L
footprint 0402S
pins: 1, 2

## GRM1555C1E4R7CA01D
designator C?  ValueDisplayed: 4.7pF  (hidden comment: GRM1555C1E4R7CA01D)
CAP, CERM, 4.7 pF, 25 V,+/- 5%, C0G/NP0, 0402; Manufacturer: MuRata; Polarized: N; CompType: Capacitor; Value: 4.7pF; U/M: EA; Cap_F: 0.0000000000047; Tolerance_%: 5; VDC_V: 25; Value2: 25V; TaMin_C: -55; TaMax_C: 125; Cap_Case: 0402; SizeArea_mm2: 0.5; SizeAreaWB_mm2: 3; SizeX_mm: 1; SizeZ_mm: 0.6; AEC Category: Q200; Green_Lifecycle: Active; Green_REACh: Passed
signal-integrity model Cap
simulation model Cap
footprint 0402
footprint 0402M
footprint 0402L
footprint 0402S
pins: 1, 2

## GRM1555C1E5R1CA01D
designator C?  ValueDisplayed: 5.1pF  (hidden comment: GRM1555C1E5R1CA01D)
CAP, CERM, 5.1 pF, 25 V,+/- 5%, C0G/NP0, 0402; Manufacturer: MuRata; Polarized: N; CompType: Capacitor; Value: 5.1pF; U/M: EA; Cap_F: 0.0000000000051; Tolerance_%: 5; VDC_V: 25; Value2: 25V; TaMin_C: -55; TaMax_C: 125; Cap_Case: 0402; SizeArea_mm2: 0.5; SizeAreaWB_mm2: 3; SizeX_mm: 1; SizeZ_mm: 0.6; AEC Category: Q200
signal-integrity model Cap
simulation model Cap
footprint 0402
footprint 0402M
footprint 0402L
footprint 0402S
pins: 1, 2

## GRM1555C1E5R6CA01D
designator C?  ValueDisplayed: 5.6pF  (hidden comment: GRM1555C1E5R6CA01D)
CAP, CERM, 5.6 pF, 25 V,+/- 5%, C0G/NP0, 0402; Manufacturer: MuRata; Polarized: N; CompType: Capacitor; Value: 5.6pF; U/M: EA; Cap_F: 0.0000000000056; Tolerance_%: 5; VDC_V: 25; Value2: 25V; TaMin_C: -55; TaMax_C: 125; Cap_Case: 0402; SizeArea_mm2: 0.5; SizeAreaWB_mm2: 3; SizeX_mm: 1; SizeZ_mm: 0.6; AEC Category: Q200
signal-integrity model Cap
simulation model Cap
footprint 0402
footprint 0402M
footprint 0402L
footprint 0402S
pins: 1, 2

## GRM1555C1E6R2CA01D
designator C?  ValueDisplayed: 6.2pF  (hidden comment: GRM1555C1E6R2CA01D)
CAP, CERM, 6.2 pF, 25 V,+/- 5%, C0G/NP0, 0402; Manufacturer: MuRata; Polarized: N; CompType: Capacitor; Value: 6.2pF; U/M: EA; Cap_F: 0.0000000000062; Tolerance_%: 5; VDC_V: 25; Value2: 25V; TaMin_C: -55; TaMax_C: 125; Cap_Case: 0402; SizeArea_mm2: 0.5; SizeAreaWB_mm2: 3; SizeX_mm: 1; SizeZ_mm: 0.6; AEC Category: Q200
signal-integrity model Cap
simulation model Cap
footprint 0402
footprint 0402M
footprint 0402L
footprint 0402S
pins: 1, 2

## GRM1555C1E6R8CA01D
designator C?  ValueDisplayed: 6.8pF  (hidden comment: GRM1555C1E6R8CA01D)
CAP, CERM, 6.8 pF, 25 V,+/- 5%, C0G/NP0, 0402; Manufacturer: MuRata; Polarized: N; CompType: Capacitor; Value: 6.8pF; U/M: EA; Cap_F: 0.0000000000068; Tolerance_%: 5; VDC_V: 25; Value2: 25V; TaMin_C: -55; TaMax_C: 125; Cap_Case: 0402; SizeArea_mm2: 0.5; SizeAreaWB_mm2: 3; SizeX_mm: 1; SizeZ_mm: 0.6; AEC Category: Q200
signal-integrity model Cap
simulation model Cap
footprint 0402
footprint 0402M
footprint 0402L
footprint 0402S
pins: 1, 2

## GRM1555C1E8R2CA01D
designator C?  ValueDisplayed: 8.2pF  (hidden comment: GRM1555C1E8R2CA01D)
CAP, CERM, 8.2 pF, 25 V,+/- 5%, C0G/NP0, 0402; Manufacturer: MuRata; Polarized: N; CompType: Capacitor; Value: 8.2pF; U/M: EA; Cap_F: 0.0000000000082; Tolerance_%: 5; VDC_V: 25; Value2: 25V; TaMin_C: -55; TaMax_C: 125; Cap_Case: 0402; SizeArea_mm2: 0.5; SizeAreaWB_mm2: 3; SizeX_mm: 1; SizeZ_mm: 0.6; AEC Category: Q200
signal-integrity model Cap
simulation model Cap
footprint 0402
footprint 0402M
footprint 0402L
footprint 0402S
pins: 1, 2

## GRM1555C1E9R1CA01D
designator C?  ValueDisplayed: 9.1pF  (hidden comment: GRM1555C1E9R1CA01D)
CAP, CERM, 9.1 pF, 25 V,+/- 5%, C0G/NP0, 0402; Manufacturer: MuRata; Polarized: N; CompType: Capacitor; Value: 9.1pF; U/M: EA; Cap_F: 0.0000000000091; Tolerance_%: 5; VDC_V: 25; Value2: 25V; TaMin_C: -55; TaMax_C: 125; Cap_Case: 0402; SizeArea_mm2: 0.5; SizeAreaWB_mm2: 3; SizeX_mm: 1; SizeZ_mm: 0.6; AEC Category: Q200
signal-integrity model Cap
simulation model Cap
footprint 0402
footprint 0402M
footprint 0402L
footprint 0402S
pins: 1, 2

## GRM1555C1E110JA01D
designator C?  ValueDisplayed: 11pF  (hidden comment: GRM1555C1E110JA01D)
CAP, CERM, 11 pF, 25 V,+/- 5%, C0G/NP0, 0402; Manufacturer: MuRata; Polarized: N; CompType: Capacitor; Value: 11pF; U/M: EA; Cap_F: 0.000000000011; Tolerance_%: 5; VDC_V: 25; Value2: 25V; TaMin_C: -55; TaMax_C: 125; Cap_Case: 0402; SizeArea_mm2: 0.5; SizeAreaWB_mm2: 3; SizeX_mm: 1; SizeZ_mm: 0.6; AEC Category: Q200
signal-integrity model Cap
simulation model Cap
footprint 0402
footprint 0402M
footprint 0402L
footprint 0402S
pins: 1, 2

## GRM1555C1E111JA01D
designator C?  ValueDisplayed: 110pF  (hidden comment: GRM1555C1E111JA01D)
CAP, CERM, 110 pF, 25 V,+/- 5%, C0G/NP0, 0402; Manufacturer: MuRata; Polarized: N; CompType: Capacitor; Value: 110pF; U/M: EA; Cap_F: 0.00000000011; Tolerance_%: 5; VDC_V: 25; Value2: 25V; TaMin_C: -55; TaMax_C: 125; Cap_Case: 0402; SizeArea_mm2: 0.5; SizeAreaWB_mm2: 3; SizeX_mm: 1; SizeZ_mm: 0.6; AEC Category: Q200
signal-integrity model Cap
simulation model Cap
footprint 0402
footprint 0402M
footprint 0402L
footprint 0402S
pins: 1, 2

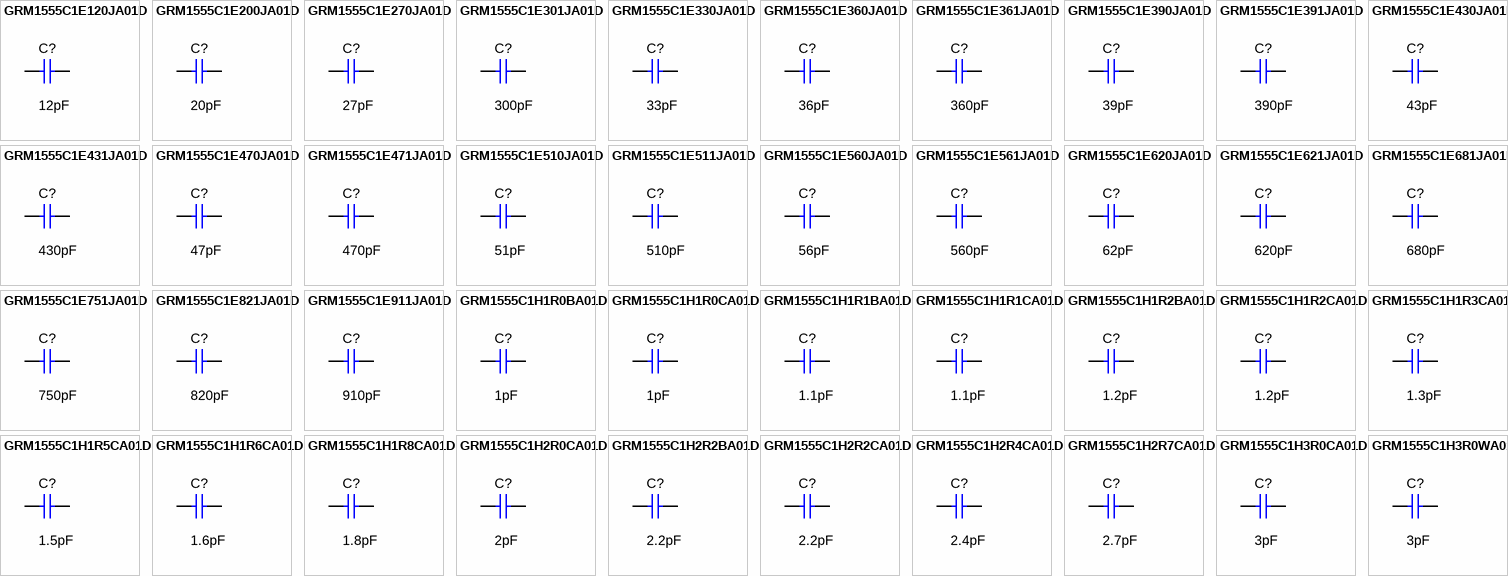
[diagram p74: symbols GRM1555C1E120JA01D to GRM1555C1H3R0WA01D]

## GRM1555C1E120JA01D
designator C?  ValueDisplayed: 12pF  (hidden comment: GRM1555C1E120JA01D)
CAP, CERM, 12 pF, 25 V,+/- 5%, C0G/NP0, 0402; Manufacturer: MuRata; Polarized: N; CompType: Capacitor; Value: 12pF; U/M: EA; Cap_F: 0.000000000012; Tolerance_%: 5; VDC_V: 25; Value2: 25V; TaMin_C: -55; TaMax_C: 125; Cap_Case: 0402; SizeArea_mm2: 0.5; SizeAreaWB_mm2: 3; SizeX_mm: 1; SizeZ_mm: 0.6; AEC Category: Q200
signal-integrity model Cap
simulation model Cap
footprint 0402
footprint 0402M
footprint 0402L
footprint 0402S
pins: 1, 2

## GRM1555C1E200JA01D
designator C?  ValueDisplayed: 20pF  (hidden comment: GRM1555C1E200JA01D)
CAP, CERM, 20 pF, 25 V,+/- 5%, C0G/NP0, 0402; Manufacturer: MuRata; Polarized: N; CompType: Capacitor; Value: 20pF; U/M: EA; Cap_F: 0.00000000002; Tolerance_%: 5; VDC_V: 25; Value2: 25V; TaMin_C: -55; TaMax_C: 125; Cap_Case: 0402; SizeArea_mm2: 0.5; SizeAreaWB_mm2: 3; SizeX_mm: 1; SizeZ_mm: 0.6; AEC Category: Q200
signal-integrity model Cap
simulation model Cap
footprint 0402
footprint 0402M
footprint 0402L
footprint 0402S
pins: 1, 2

## GRM1555C1E270JA01D
designator C?  ValueDisplayed: 27pF  (hidden comment: GRM1555C1E270JA01D)
CAP, CERM, 27 pF, 25 V,+/- 5%, C0G/NP0, 0402; Manufacturer: MuRata; Polarized: N; CompType: Capacitor; Value: 27pF; U/M: EA; Cap_F: 0.000000000027; Tolerance_%: 5; VDC_V: 25; Value2: 25V; TaMin_C: -55; TaMax_C: 125; Cap_Case: 0402; SizeArea_mm2: 0.5; SizeAreaWB_mm2: 3; SizeX_mm: 1; SizeZ_mm: 0.6; AEC Category: Q200
signal-integrity model Cap
simulation model Cap
footprint 0402
footprint 0402M
footprint 0402L
footprint 0402S
pins: 1, 2

## GRM1555C1E301JA01D
designator C?  ValueDisplayed: 300pF  (hidden comment: GRM1555C1E301JA01D)
CAP, CERM, 300 pF, 25 V,+/- 5%, C0G/NP0, 0402; Manufacturer: MuRata; Polarized: N; CompType: Capacitor; Value: 300pF; U/M: EA; Cap_F: 0.0000000003; Tolerance_%: 5; VDC_V: 25; Value2: 25V; TaMin_C: -55; TaMax_C: 125; Cap_Case: 0402; SizeArea_mm2: 0.5; SizeAreaWB_mm2: 3; SizeX_mm: 1; SizeZ_mm: 0.6; AEC Category: Q200; Green_Lifecycle: Active; Green_REACh: Passed
signal-integrity model Cap
simulation model Cap
footprint 0402
footprint 0402M
footprint 0402L
footprint 0402S
pins: 1, 2

## GRM1555C1E330JA01D
designator C?  ValueDisplayed: 33pF  (hidden comment: GRM1555C1E330JA01D)
CAP, CERM, 33 pF, 25 V,+/- 5%, C0G/NP0, 0402; Manufacturer: MuRata; Polarized: N; CompType: Capacitor; Value: 33pF; U/M: EA; Cap_F: 0.000000000033; Tolerance_%: 5; VDC_V: 25; Value2: 25V; TaMin_C: -55; TaMax_C: 125; Cap_Case: 0402; SizeArea_mm2: 0.5; SizeAreaWB_mm2: 3; SizeX_mm: 1; SizeZ_mm: 0.6; AEC Category: Q200; Green_Lifecycle: Active; Green_REACh: Passed
signal-integrity model Cap
simulation model Cap
footprint 0402
footprint 0402M
footprint 0402L
footprint 0402S
pins: 1, 2

## GRM1555C1E360JA01D
designator C?  ValueDisplayed: 36pF  (hidden comment: GRM1555C1E360JA01D)
CAP, CERM, 36 pF, 25 V,+/- 5%, C0G/NP0, 0402; Manufacturer: MuRata; Polarized: N; CompType: Capacitor; Value: 36pF; U/M: EA; Cap_F: 0.000000000036; Tolerance_%: 5; VDC_V: 25; Value2: 25V; TaMin_C: -55; TaMax_C: 125; Cap_Case: 0402; SizeArea_mm2: 0.5; SizeAreaWB_mm2: 3; SizeX_mm: 1; SizeZ_mm: 0.6; AEC Category: Q200
signal-integrity model Cap
simulation model Cap
footprint 0402
footprint 0402M
footprint 0402L
footprint 0402S
pins: 1, 2

## GRM1555C1E361JA01D
designator C?  ValueDisplayed: 360pF  (hidden comment: GRM1555C1E361JA01D)
CAP, CERM, 360 pF, 25 V,+/- 5%, C0G/NP0, 0402; Manufacturer: MuRata; Polarized: N; CompType: Capacitor; Value: 360pF; U/M: EA; Cap_F: 0.00000000036; Tolerance_%: 5; VDC_V: 25; Value2: 25V; TaMin_C: -55; TaMax_C: 125; Cap_Case: 0402; SizeArea_mm2: 0.5; SizeAreaWB_mm2: 3; SizeX_mm: 1; SizeZ_mm: 0.6; AEC Category: Q200
signal-integrity model Cap
simulation model Cap
footprint 0402
footprint 0402M
footprint 0402L
footprint 0402S
pins: 1, 2

## GRM1555C1E390JA01D
designator C?  ValueDisplayed: 39pF  (hidden comment: GRM1555C1E390JA01D)
CAP, CERM, 39 pF, 25 V,+/- 5%, C0G/NP0, 0402; Manufacturer: MuRata; Polarized: N; CompType: Capacitor; Value: 39pF; U/M: EA; Cap_F: 0.000000000039; Tolerance_%: 5; VDC_V: 25; Value2: 25V; TaMin_C: -55; TaMax_C: 125; Cap_Case: 0402; SizeArea_mm2: 0.5; SizeAreaWB_mm2: 3; SizeX_mm: 1; SizeZ_mm: 0.6; AEC Category: Q200
signal-integrity model Cap
simulation model Cap
footprint 0402
footprint 0402M
footprint 0402L
footprint 0402S
pins: 1, 2

## GRM1555C1E391JA01D
designator C?  ValueDisplayed: 390pF  (hidden comment: GRM1555C1E391JA01D)
CAP, CERM, 390 pF, 25 V,+/- 5%, C0G/NP0, 0402; Manufacturer: MuRata; Polarized: N; CompType: Capacitor; Value: 390pF; U/M: EA; Cap_F: 0.00000000039; Tolerance_%: 5; VDC_V: 25; Value2: 25V; TaMin_C: -55; TaMax_C: 125; Cap_Case: 0402; SizeArea_mm2: 0.5; SizeAreaWB_mm2: 3; SizeX_mm: 1; SizeZ_mm: 0.6; AEC Category: Q200
signal-integrity model Cap
simulation model Cap
footprint 0402
footprint 0402M
footprint 0402L
footprint 0402S
pins: 1, 2

## GRM1555C1E430JA01D
designator C?  ValueDisplayed: 43pF  (hidden comment: GRM1555C1E430JA01D)
CAP, CERM, 43 pF, 25 V,+/- 5%, C0G/NP0, 0402; Manufacturer: MuRata; Polarized: N; CompType: Capacitor; Value: 43pF; U/M: EA; Cap_F: 0.000000000043; Tolerance_%: 5; VDC_V: 25; Value2: 25V; TaMin_C: -55; TaMax_C: 125; Cap_Case: 0402; SizeArea_mm2: 0.5; SizeAreaWB_mm2: 3; SizeX_mm: 1; SizeZ_mm: 0.6; AEC Category: Q200
signal-integrity model Cap
simulation model Cap
footprint 0402
footprint 0402M
footprint 0402L
footprint 0402S
pins: 1, 2

## GRM1555C1E431JA01D
designator C?  ValueDisplayed: 430pF  (hidden comment: GRM1555C1E431JA01D)
CAP, CERM, 430 pF, 25 V,+/- 5%, C0G/NP0, 0402; Manufacturer: MuRata; Polarized: N; CompType: Capacitor; Value: 430pF; U/M: EA; Cap_F: 0.00000000043; Tolerance_%: 5; VDC_V: 25; Value2: 25V; TaMin_C: -55; TaMax_C: 125; Cap_Case: 0402; SizeArea_mm2: 0.5; SizeAreaWB_mm2: 3; SizeX_mm: 1; SizeZ_mm: 0.6; AEC Category: Q200
signal-integrity model Cap
simulation model Cap
footprint 0402
footprint 0402M
footprint 0402L
footprint 0402S
pins: 1, 2

## GRM1555C1E470JA01D
designator C?  ValueDisplayed: 47pF  (hidden comment: GRM1555C1E470JA01D)
CAP, CERM, 47 pF, 25 V,+/- 5%, C0G/NP0, 0402; Manufacturer: MuRata; Polarized: N; CompType: Capacitor; Value: 47pF; U/M: EA; Cap_F: 0.000000000047; Tolerance_%: 5; VDC_V: 25; Value2: 25V; TaMin_C: -55; TaMax_C: 125; Cap_Case: 0402; SizeArea_mm2: 0.5; SizeAreaWB_mm2: 3; SizeX_mm: 1; SizeZ_mm: 0.6; AEC Category: Q200; Green_Lifecycle: Active; Green_REACh: Passed
signal-integrity model Cap
simulation model Cap
footprint 0402
footprint 0402M
footprint 0402L
footprint 0402S
pins: 1, 2

## GRM1555C1E471JA01D
designator C?  ValueDisplayed: 470pF  (hidden comment: GRM1555C1E471JA01D)
CAP, CERM, 470 pF, 25 V,+/- 5%, C0G/NP0, 0402; Manufacturer: MuRata; Polarized: N; CompType: Capacitor; Value: 470pF; U/M: EA; Cap_F: 0.00000000047; Tolerance_%: 5; VDC_V: 25; Value2: 25V; TaMin_C: -55; TaMax_C: 125; Cap_Case: 0402; SizeArea_mm2: 0.5; SizeAreaWB_mm2: 3; SizeX_mm: 1; SizeZ_mm: 0.6; AEC Category: Q200
signal-integrity model Cap
simulation model Cap
footprint 0402
footprint 0402M
footprint 0402L
footprint 0402S
pins: 1, 2

## GRM1555C1E510JA01D
designator C?  ValueDisplayed: 51pF  (hidden comment: GRM1555C1E510JA01D)
CAP, CERM, 51 pF, 25 V,+/- 5%, C0G/NP0, 0402; Manufacturer: MuRata; Polarized: N; CompType: Capacitor; Value: 51pF; U/M: EA; Cap_F: 0.000000000051; Tolerance_%: 5; VDC_V: 25; Value2: 25V; TaMin_C: -55; TaMax_C: 125; Cap_Case: 0402; SizeArea_mm2: 0.5; SizeAreaWB_mm2: 3; SizeX_mm: 1; SizeZ_mm: 0.6; AEC Category: Q200
signal-integrity model Cap
simulation model Cap
footprint 0402
footprint 0402M
footprint 0402L
footprint 0402S
pins: 1, 2

## GRM1555C1E511JA01D
designator C?  ValueDisplayed: 510pF  (hidden comment: GRM1555C1E511JA01D)
CAP, CERM, 510 pF, 25 V,+/- 5%, C0G/NP0, 0402; Manufacturer: MuRata; Polarized: N; CompType: Capacitor; Value: 510pF; U/M: EA; Cap_F: 0.00000000051; Tolerance_%: 5; VDC_V: 25; Value2: 25V; TaMin_C: -55; TaMax_C: 125; Cap_Case: 0402; SizeArea_mm2: 0.5; SizeAreaWB_mm2: 3; SizeX_mm: 1; SizeZ_mm: 0.6; AEC Category: Q200
signal-integrity model Cap
simulation model Cap
footprint 0402
footprint 0402M
footprint 0402L
footprint 0402S
pins: 1, 2

## GRM1555C1E560JA01D
designator C?  ValueDisplayed: 56pF  (hidden comment: GRM1555C1E560JA01D)
CAP, CERM, 56 pF, 25 V,+/- 5%, C0G/NP0, 0402; Manufacturer: MuRata; Polarized: N; CompType: Capacitor; Value: 56pF; U/M: EA; Cap_F: 0.000000000056; Tolerance_%: 5; VDC_V: 25; Value2: 25V; TaMin_C: -55; TaMax_C: 125; Cap_Case: 0402; SizeArea_mm2: 0.5; SizeAreaWB_mm2: 3; SizeX_mm: 1; SizeZ_mm: 0.6; AEC Category: Q200
signal-integrity model Cap
simulation model Cap
footprint 0402
footprint 0402M
footprint 0402L
footprint 0402S
pins: 1, 2

## GRM1555C1E561JA01D
designator C?  ValueDisplayed: 560pF  (hidden comment: GRM1555C1E561JA01D)
CAP, CERM, 560 pF, 25 V,+/- 5%, C0G/NP0, 0402; Manufacturer: MuRata; Polarized: N; CompType: Capacitor; Value: 560pF; U/M: EA; Cap_F: 0.00000000056; Tolerance_%: 5; VDC_V: 25; Value2: 25V; TaMin_C: -55; TaMax_C: 125; Cap_Case: 0402; SizeArea_mm2: 0.5; SizeAreaWB_mm2: 3; SizeX_mm: 1; SizeZ_mm: 0.6; AEC Category: Q200
signal-integrity model Cap
simulation model Cap
footprint 0402
footprint 0402M
footprint 0402L
footprint 0402S
pins: 1, 2

## GRM1555C1E620JA01D
designator C?  ValueDisplayed: 62pF  (hidden comment: GRM1555C1E620JA01D)
CAP, CERM, 62 pF, 25 V,+/- 5%, C0G/NP0, 0402; Manufacturer: MuRata; Polarized: N; CompType: Capacitor; Value: 62pF; U/M: EA; Cap_F: 0.000000000062; Tolerance_%: 5; VDC_V: 25; Value2: 25V; TaMin_C: -55; TaMax_C: 125; Cap_Case: 0402; SizeArea_mm2: 0.5; SizeAreaWB_mm2: 3; SizeX_mm: 1; SizeZ_mm: 0.6; AEC Category: Q200
signal-integrity model Cap
simulation model Cap
footprint 0402
footprint 0402M
footprint 0402L
footprint 0402S
pins: 1, 2

## GRM1555C1E621JA01D
designator C?  ValueDisplayed: 620pF  (hidden comment: GRM1555C1E621JA01D)
CAP, CERM, 620 pF, 25 V,+/- 5%, C0G/NP0, 0402; Manufacturer: MuRata; Polarized: N; CompType: Capacitor; Value: 620pF; U/M: EA; Cap_F: 0.00000000062; Tolerance_%: 5; VDC_V: 25; Value2: 25V; TaMin_C: -55; TaMax_C: 125; Cap_Case: 0402; SizeArea_mm2: 0.5; SizeAreaWB_mm2: 3; SizeX_mm: 1; SizeZ_mm: 0.6; AEC Category: Q200
signal-integrity model Cap
simulation model Cap
footprint 0402
footprint 0402M
footprint 0402L
footprint 0402S
pins: 1, 2

## GRM1555C1E681JA01D
designator C?  ValueDisplayed: 680pF  (hidden comment: GRM1555C1E681JA01D)
CAP, CERM, 680 pF, 25 V,+/- 5%, C0G/NP0, 0402; Manufacturer: MuRata; Polarized: N; CompType: Capacitor; Value: 680pF; U/M: EA; Cap_F: 0.00000000068; Tolerance_%: 5; VDC_V: 25; Value2: 25V; TaMin_C: -55; TaMax_C: 125; Cap_Case: 0402; SizeArea_mm2: 0.5; SizeAreaWB_mm2: 3; SizeX_mm: 1; SizeZ_mm: 0.6; AEC Category: Q200
signal-integrity model Cap
simulation model Cap
footprint 0402
footprint 0402M
footprint 0402L
footprint 0402S
pins: 1, 2

## GRM1555C1E751JA01D
designator C?  ValueDisplayed: 750pF  (hidden comment: GRM1555C1E751JA01D)
CAP, CERM, 750 pF, 25 V,+/- 5%, C0G/NP0, 0402; Manufacturer: MuRata; Polarized: N; CompType: Capacitor; Value: 750pF; U/M: EA; Cap_F: 0.00000000075; Tolerance_%: 5; VDC_V: 25; Value2: 25V; TaMin_C: -55; TaMax_C: 125; Cap_Case: 0402; SizeArea_mm2: 0.5; SizeAreaWB_mm2: 3; SizeX_mm: 1; SizeZ_mm: 0.6; AEC Category: Q200
signal-integrity model Cap
simulation model Cap
footprint 0402
footprint 0402M
footprint 0402L
footprint 0402S
pins: 1, 2

## GRM1555C1E821JA01D
designator C?  ValueDisplayed: 820pF  (hidden comment: GRM1555C1E821JA01D)
CAP, CERM, 820 pF, 25 V,+/- 5%, C0G/NP0, 0402; Manufacturer: MuRata; Polarized: N; CompType: Capacitor; Value: 820pF; U/M: EA; Cap_F: 0.00000000082; Tolerance_%: 5; VDC_V: 25; Value2: 25V; TaMin_C: -55; TaMax_C: 125; Cap_Case: 0402; SizeArea_mm2: 0.5; SizeAreaWB_mm2: 3; SizeX_mm: 1; SizeZ_mm: 0.6; AEC Category: Q200
signal-integrity model Cap
simulation model Cap
footprint 0402
footprint 0402M
footprint 0402L
footprint 0402S
pins: 1, 2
